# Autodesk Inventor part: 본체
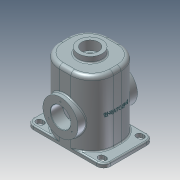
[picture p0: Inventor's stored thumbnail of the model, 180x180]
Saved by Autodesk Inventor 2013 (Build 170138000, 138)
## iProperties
Company: 한국ATC센터
Created: 2014-10
Part Number: 본체
Document SubType Name: Modeling
Designer: 한국ATC센터
Density: 1 g/cm^3
Material: 일반
Mass: 1088.52 g
Surface Area: 2150.09 cm^2
Volume: 1088.52 cm^3
Author: KYOUNG IL JANG
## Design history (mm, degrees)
sketch "스케치1"
  geometry: L1 (-70, 65)-(70, 65); L2 (70, 65)-(70, -65); L3 (70, -65)-(-70, -65); L4 (-70, -65)-(-70, 65); 3 further points
  constraints: 8 end point, 2 midpoint, 2 parallel, 1 horizontal, 1 horizontal alignment, 1 perpendicular, 1 vertical alignment
  dimensions: "d0" = 140 distance of L2.end L3.end; "d68" = 130 distance of L3.end L1.start
extrude "돌출1" new body sketch "스케치1" distance "d1" = 180; taper "d2" = 0 deg
fillet "모깎기1" dims "d3" = 55
feature "쉘1" dims "d4" = 10
sketch "스케치2"
  geometry: L1 (-70, 10)-(-70, -10) reference; L2 (-15, -65)-(-82, -65); L3 (-82, 65)-(-15, 65); L4 (-83, 57)-(-78, 57); L5 (-78, 41)-(-83, 41); L6 (-100, 47)-(-100, -47); A1 r 55 centre (-15, 10) between (-15, 65) and (-70, 10) reference; A2 r 55 centre (-15, -10) between (-70, -10) and (-15, -65) reference; A3 r 8 centre (-78, 49) between (-78, 41) and (-78, 57); A4 r 8 centre (-83, 49) between (-83, 57) and (-83, 41); A5 r 18 centre (-82, 47) between (-82, 65) and (-100, 47); A6 r 18 centre (-82, -47) between (-100, -47) and (-82, -65); 1 further point
  constraints: 10 end point, 9 tangent, 8 point on circle, 4 centre point, 2 parallel, 2 perpendicular, 1 equal radius
  dimensions: "d6" = 49 vertical distance of point (0, 0) A3.centre; "d8" = 16 distance between parallel lines of L4 L5; "d64" = 18 radius of A5; "d65" = 8 distance from line of A3.centre L1; "d66" = 30 distance between parallel lines of L6 L1; "d67" = 5 distance of A4.centre A3.centre
extrude "돌출2" join sketch "스케치2" distance "d9" = 10; taper "d10" = 0 deg
extrude "돌출3" cut sketch "스케치2" stored distance "d11" = 10; taper "d12" = 0 deg
sketch "스케치3"
  geometry: L1 (-65, 10)-(-65, 180) reference; L2 (-55, 0)-(-55, 170) reference; L3 (-77, 75)-(-45, 75); L4 (10, 0)-(-10, 0) reference; L5 (-77, 75)-(-77, 120.5); L6 (-77, 120.5)-(-55, 120.5); L7 (-55, 120.5)-(-45, 110.5); L8 (-45, 110.5)-(-45, 75); 3 further points
  constraints: 10 end point, 4 perpendicular, 1 point on line
  dimensions: "d13" = 75 distance between parallel lines of L3 L4; "d14" = 12 distance from line of L1 L3.start; "d15" = 10 distance from line of L3.end L2; "d16" = 91 diameter of L6 L3; "d17" = 135 deg angle of L7 L2
revolve "회전1" sketch "스케치3" stored, may be unused: angle "d18" = 90 deg
sketch "스케치4"
  geometry: C1 r 45.5 at (0, 0) reference; 2 further points
  constraints: 1 vertical alignment
  dimensions: "d19" = 35 distance of C1.centre point (0, 35)
hole "구멍1" sketch "스케치4" at (0, 35) diameter "d20" = 3.459; stored, may be unused: countersink angle "d24" = 90 deg, drill point angle "d26" = 118 deg; dims "d21" = 13, "d22" = 4, "d23" = 2, "d25" = 16
fillet "모깎기2" dims "d30" = 3
hole "구멍2" diameter "d33" = 52; stored, may be unused: countersink angle "d37" = 90 deg, drill point angle "d39" = 118 deg; dims "d31" = 10, "d32" = 10, "d34" = 13, "d35" = 4, "d36" = 2, "d38" = 16
sketch "스케치5"
  geometry: C1 r 31 at (0, 0); 1 further point
  constraints: 1 centre point, 1 coincident
  dimensions: "d40" = 62 diameter of C1
extrude "돌출4" join sketch "스케치5" distance "d41" = 15; taper "d42" = 0 deg
hole "구멍3" diameter "d45" = 43; stored, may be unused: countersink angle "d49" = 90 deg, drill point angle "d51" = 118 deg; dims "d43" = 10, "d44" = 10, "d46" = 13, "d47" = 4, "d48" = 2, "d50" = 16
fillet "모깎기3" dims "d52" = 3
fillet "모깎기4" dims "d53" = 3
chamfer "모따기1" distance "d55" = 1; stored, may be unused: second distance "d56" = 2, angle "d57" = 45 deg
sketch "스케치6"
  geometry: 2 further points
  constraints: 1 vertical alignment, 1 other
  dimensions: "d71" = 90 distance of point (0, 0) point (0, 90)
feature "엠보싱2" sketch "스케치6" dims "d0" = 140, "d68" = 130, "d72" = 1, "d73" = 0
fillet "모깎기6" dims "d74" = 10
sketch "스케치7"
  geometry: C1 r 15 at (0, 0); C2 r 21.5 at (0, 0) reference; C3 r 25 at (0, 0); 1 further point
  constraints: 2 centre point, 2 coincident
  dimensions: "d61" = 30 diameter of C1; "d75" = 50 diameter of C3
extrude "돌출5" join sketch "스케치7" distance "d62" = 10; taper "d63" = 0 deg
feature "면 이동1" dims "d76" = 1
node "솔리드1"
mirror "대칭1"
mirror "대칭2"
pattern_circular "원형 패턴1" dims angle "d28" = 360 deg
mirror "대칭3"
